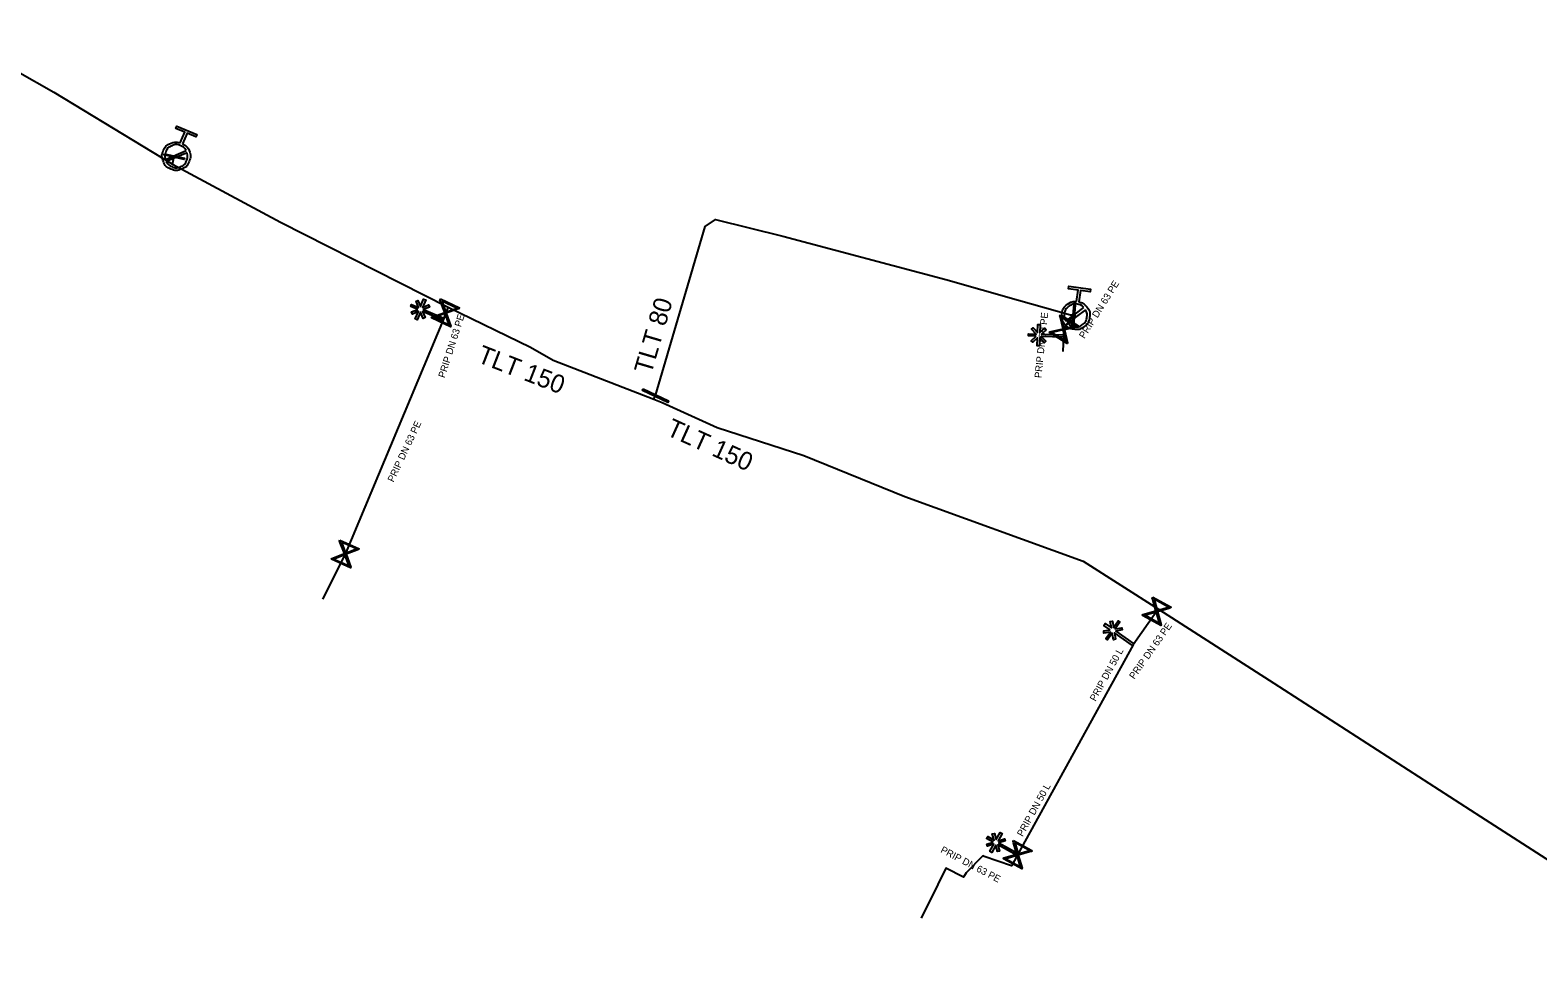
# Model space of a CAD drawing. Extents: x -643544 to -637295, y -1119190 to -1111715.
# Drawn here: x -642788.2 to -642680.3, y -1114459.1 to -1114393 of the extents above; entities that cross this region are included whole.
import ezdxf

# ---------------------------------------------------------------- set-up
doc = ezdxf.new("R2010")
doc.units = 0
for name, color, linetype in [('Default', 7, 'Continuous'), ('VP Hydrant', 7, 'Continuous'), ('VP Popis přípojky', 7, 'Continuous'), ('VP Přípojka', 7, 'Continuous'), ('VP Změna materiálu', 7, 'Continuous'), ('VP Řad', 7, 'Continuous'), ('VP Řad - popis', 7, 'Continuous'), ('VP Šoupě', 7, 'Continuous')]:
    doc.layers.add(name, color=color, linetype=linetype)

msp = doc.modelspace()

# ---------------------------------------------------------------- linework, layer by layer
at = {"layer": 'Default'}
for points in [[(-642777.26, -1114401.17), (-642776.93, -1114401.34), (-642776.79, -1114401.68), (-642776.64, -1114402.06), (-642776.8, -1114402.44), (-642776.95, -1114402.83), (-642777.34, -1114402.98), (-642777.72, -1114403.14), (-642778.1, -1114402.98), (-642778.48, -1114402.83), (-642778.64, -1114402.44), (-642778.8, -1114402.06), (-642778.65, -1114401.68), (-642778.49, -1114401.3), (-642778.11, -1114401.14), (-642777.77, -1114400.99), (-642777.43, -1114401.1)], [(-642777.01, -1114401.66), (-642777.14, -1114401.42), (-642777.41, -1114401.31), (-642777.72, -1114401.18), (-642778.03, -1114401.31), (-642778.34, -1114401.44), (-642778.47, -1114401.75), (-642778.58, -1114402.02), (-642778.5, -1114402.29)], [(-642778.43, -1114402.45), (-642778.3, -1114402.7), (-642778.03, -1114402.81), (-642777.72, -1114402.94), (-642777.41, -1114402.81), (-642777.1, -1114402.68), (-642776.97, -1114402.37), (-642776.86, -1114402.1), (-642776.94, -1114401.83)], [(-642713.12, -1114412.48), (-642712.77, -1114412.56), (-642712.55, -1114412.85), (-642712.3, -1114413.18), (-642712.36, -1114413.59), (-642712.42, -1114414), (-642712.75, -1114414.25), (-642713.08, -1114414.5), (-642713.49, -1114414.44), (-642713.9, -1114414.38), (-642714.15, -1114414.05), (-642714.4, -1114413.72), (-642714.34, -1114413.31), (-642714.28, -1114412.9), (-642713.95, -1114412.65), (-642713.66, -1114412.43), (-642713.3, -1114412.45)], [(-642712.76, -1114412.89), (-642712.95, -1114412.69), (-642713.24, -1114412.64), (-642713.57, -1114412.6), (-642713.84, -1114412.8), (-642714.11, -1114413), (-642714.16, -1114413.33), (-642714.2, -1114413.62), (-642714.05, -1114413.86)], [(-642713.94, -1114414.01), (-642713.75, -1114414.21), (-642713.47, -1114414.25), (-642713.13, -1114414.3), (-642712.86, -1114414.1), (-642712.6, -1114413.9), (-642712.55, -1114413.56), (-642712.51, -1114413.28), (-642712.65, -1114413.04)]]:
    msp.add_open_spline(points, degree=3, dxfattribs=at)
at = {"layer": 'VP Hydrant'}
for points in [[(-642777.43, -1114401.1), (-642777.11, -1114400.35), (-642777.75, -1114400.08), (-642777.68, -1114399.91), (-642776.24, -1114400.51), (-642776.31, -1114400.68), (-642776.94, -1114400.42), (-642777.26, -1114401.17)], [(-642778.5, -1114402.29), (-642777.01, -1114401.66)], [(-642776.94, -1114401.83), (-642778.43, -1114402.45)], [(-642713.3, -1114412.45), (-642713.18, -1114411.64), (-642713.87, -1114411.54), (-642713.84, -1114411.36), (-642712.29, -1114411.58), (-642712.32, -1114411.76), (-642713, -1114411.67), (-642713.12, -1114412.48)], [(-642714.05, -1114413.86), (-642712.76, -1114412.89)], [(-642712.65, -1114413.04), (-642713.94, -1114414.01)]]:
    msp.add_lwpolyline(points, dxfattribs=at)
at = {"layer": 'VP Přípojka'}
for points in [[(-642777.99, -1114402.62), (-642777.87, -1114402.09), (-642777.72, -1114402.06)], [(-642758.6, -1114413.71), (-642765.63, -1114430.52), (-642767.25, -1114433.75)], [(-642758.25, -1114412.85), (-642758.46, -1114413.27), (-642758.6, -1114413.71)], [(-642713.61, -1114413.42), (-642713.65, -1114413.55), (-642714.21, -1114414.44), (-642714.23, -1114414.93)], [(-642714.23, -1114414.93), (-642714.27, -1114416.04)], [(-642707.44, -1114434.46), (-642707.55, -1114434.62), (-642709.24, -1114437.01)], [(-642709.24, -1114437.01), (-642717.51, -1114452.03)], [(-642717.51, -1114452.03), (-642717.73, -1114452.44), (-642717.94, -1114452.83), (-642719.91, -1114452.16), (-642720.01, -1114452.11), (-642721.18, -1114453.32), (-642721.38, -1114453.63), (-642722.64, -1114452.99), (-642723.22, -1114454.17), (-642724.41, -1114456.58)]]:
    msp.add_lwpolyline(points, dxfattribs=at)
at = {"layer": 'VP Změna materiálu'}
for points in [[(-642760.44, -1114413.02), (-642760.94, -1114412.81), (-642760.88, -1114412.67), (-642760.38, -1114412.88), (-642760.56, -1114412.44), (-642760.42, -1114412.39), (-642760.24, -1114412.82), (-642760.02, -1114412.28), (-642759.87, -1114412.34), (-642760.1, -1114412.88), (-642759.66, -1114412.7), (-642759.6, -1114412.85), (-642760.03, -1114413.02), (-642758.57, -1114413.64), (-642758.63, -1114413.78), (-642760.09, -1114413.17), (-642759.91, -1114413.6), (-642760.06, -1114413.66), (-642760.24, -1114413.22), (-642760.47, -1114413.76), (-642760.61, -1114413.7), (-642760.39, -1114413.17), (-642760.82, -1114413.35), (-642760.88, -1114413.2), (-642760.44, -1114413.02)], [(-642716.19, -1114414.93), (-642716.73, -1114414.91), (-642716.72, -1114414.76), (-642716.19, -1114414.78), (-642716.51, -1114414.43), (-642716.39, -1114414.33), (-642716.08, -1114414.67), (-642716.06, -1114414.09), (-642715.9, -1114414.1), (-642715.92, -1114414.68), (-642715.57, -1114414.36), (-642715.47, -1114414.47), (-642715.81, -1114414.79), (-642714.22, -1114414.84), (-642714.23, -1114415), (-642715.82, -1114414.95), (-642715.49, -1114415.29), (-642715.61, -1114415.4), (-642715.93, -1114415.05), (-642715.95, -1114415.63), (-642716.11, -1114415.63), (-642716.09, -1114415.05), (-642716.43, -1114415.37), (-642716.53, -1114415.26), (-642716.19, -1114414.93)], [(-642710.89, -1114435.94), (-642711.33, -1114435.63), (-642711.24, -1114435.5), (-642710.8, -1114435.81), (-642710.88, -1114435.35), (-642710.73, -1114435.32), (-642710.65, -1114435.78), (-642710.31, -1114435.31), (-642710.19, -1114435.4), (-642710.52, -1114435.88), (-642710.06, -1114435.8), (-642710.03, -1114435.95), (-642710.49, -1114436.03), (-642709.19, -1114436.94), (-642709.28, -1114437.07), (-642710.58, -1114436.16), (-642710.5, -1114436.62), (-642710.65, -1114436.65), (-642710.74, -1114436.18), (-642711.07, -1114436.66), (-642711.2, -1114436.57), (-642710.87, -1114436.1), (-642711.33, -1114436.18), (-642711.35, -1114436.02), (-642710.89, -1114435.94)], [(-642719.26, -1114451.14), (-642719.73, -1114450.88), (-642719.65, -1114450.74), (-642719.18, -1114451), (-642719.32, -1114450.55), (-642719.17, -1114450.51), (-642719.04, -1114450.95), (-642718.76, -1114450.45), (-642718.62, -1114450.52), (-642718.9, -1114451.04), (-642718.45, -1114450.9), (-642718.41, -1114451.05), (-642718.85, -1114451.18), (-642717.46, -1114451.95), (-642717.54, -1114452.08), (-642718.93, -1114451.32), (-642718.8, -1114451.77), (-642718.95, -1114451.81), (-642719.08, -1114451.36), (-642719.36, -1114451.87), (-642719.5, -1114451.79), (-642719.22, -1114451.29), (-642719.67, -1114451.42), (-642719.71, -1114451.27), (-642719.26, -1114451.14)]]:
    msp.add_lwpolyline(points, dxfattribs=at)
at = {"layer": 'VP Řad'}
for points in [[(-642794.3, -1114393.04), (-642786.48, -1114397.48), (-642777.99, -1114402.62), (-642770.26, -1114406.77), (-642758.25, -1114412.85), (-642752.38, -1114415.72), (-642750.74, -1114416.66), (-642743.55, -1114419.45), (-642742.94, -1114419.68), (-642739, -1114421.46), (-642732.82, -1114423.48), (-642725.58, -1114426.4), (-642712.82, -1114431.02), (-642707.44, -1114434.46), (-642699.18, -1114439.75), (-642684.39, -1114449.31), (-642669.1, -1114459.12)], [(-642743.55, -1114419.45), (-642743.43, -1114419.19), (-642739.87, -1114407.08), (-642739.12, -1114406.59), (-642734.32, -1114407.77), (-642722.65, -1114410.88), (-642717.44, -1114412.35), (-642713.73, -1114413.41), (-642713.61, -1114413.42), (-642713.49, -1114413.43), (-642713.35, -1114413.45)]]:
    msp.add_lwpolyline(points, dxfattribs=at)
at = {"layer": 'VP Šoupě'}
for points in [[(-642778.59, -1114401.88), (-642777.13, -1114402.21), (-642777.15, -1114402.3), (-642778.61, -1114401.97), (-642778.59, -1114401.88)], [(-642758.82, -1114412.27), (-642757.46, -1114412.91), (-642757.49, -1114412.97), (-642757.61, -1114413.01), (-642758.4, -1114413.29), (-642758.07, -1114414.21), (-642758.1, -1114414.27), (-642759.46, -1114413.63), (-642759.43, -1114413.57), (-642758.51, -1114413.24), (-642758.8, -1114412.45), (-642758.85, -1114412.33), (-642758.82, -1114412.27)], [(-642758.72, -1114412.42), (-642758.43, -1114413.21), (-642757.64, -1114412.93), (-642758.72, -1114412.42)], [(-642713.38, -1114412.69), (-642713.51, -1114414.18), (-642713.6, -1114414.17), (-642713.47, -1114412.68), (-642713.38, -1114412.69)], [(-642758.2, -1114414.12), (-642758.48, -1114413.32), (-642759.28, -1114413.61), (-642758.2, -1114414.12)], [(-642714.45, -1114413.41), (-642713.18, -1114414.2), (-642713.21, -1114414.26), (-642713.34, -1114414.28), (-642714.16, -1114414.47), (-642713.94, -1114415.42), (-642713.97, -1114415.47), (-642715.24, -1114414.67), (-642715.21, -1114414.62), (-642714.26, -1114414.41), (-642714.45, -1114413.59), (-642714.48, -1114413.46), (-642714.45, -1114413.41)], [(-642714.36, -1114413.57), (-642714.18, -1114414.39), (-642713.36, -1114414.2), (-642714.36, -1114413.57)], [(-642714.05, -1114415.31), (-642714.24, -1114414.49), (-642715.06, -1114414.68), (-642714.05, -1114415.31)], [(-642744.31, -1114418.71), (-642742.5, -1114419.55), (-642742.55, -1114419.67), (-642744.36, -1114418.83), (-642744.31, -1114418.71)], [(-642766.01, -1114429.53), (-642764.64, -1114430.14), (-642764.67, -1114430.2), (-642764.79, -1114430.24), (-642765.57, -1114430.54), (-642765.22, -1114431.45), (-642765.25, -1114431.51), (-642766.62, -1114430.9), (-642766.59, -1114430.84), (-642765.68, -1114430.49), (-642765.99, -1114429.71), (-642766.03, -1114429.59), (-642766.01, -1114429.53)], [(-642765.9, -1114429.68), (-642765.6, -1114430.46), (-642764.82, -1114430.16), (-642765.9, -1114429.68)], [(-642765.35, -1114431.36), (-642765.65, -1114430.58), (-642766.44, -1114430.88), (-642765.35, -1114431.36)], [(-642707.84, -1114433.6), (-642706.53, -1114434.33), (-642706.56, -1114434.38), (-642706.69, -1114434.42), (-642707.5, -1114434.65), (-642707.23, -1114435.58), (-642707.26, -1114435.64), (-642708.57, -1114434.91), (-642708.54, -1114434.85), (-642707.61, -1114434.59), (-642707.84, -1114433.78), (-642707.88, -1114433.66), (-642707.84, -1114433.6)], [(-642707.75, -1114433.76), (-642707.52, -1114434.56), (-642706.72, -1114434.33), (-642707.75, -1114433.76)], [(-642707.35, -1114435.48), (-642707.58, -1114434.67), (-642708.39, -1114434.9), (-642707.35, -1114435.48)], [(-642717.8, -1114451.01), (-642716.49, -1114451.74), (-642716.52, -1114451.8), (-642716.65, -1114451.83), (-642717.46, -1114452.06), (-642717.19, -1114452.99), (-642717.22, -1114453.05), (-642718.53, -1114452.32), (-642718.5, -1114452.26), (-642717.56, -1114452), (-642717.8, -1114451.19), (-642717.83, -1114451.07), (-642717.8, -1114451.01)], [(-642717.71, -1114451.17), (-642717.48, -1114451.97), (-642716.67, -1114451.74), (-642717.71, -1114451.17)], [(-642717.31, -1114452.89), (-642717.54, -1114452.08), (-642718.35, -1114452.32), (-642717.31, -1114452.89)]]:
    msp.add_lwpolyline(points, dxfattribs=at)

# ---------------------------------------------------------------- texts
at = {"layer": 'VP Popis přípojky'}
for s, rotation, p in [('PRIP DN 63 PE', 57.8214, (-642712.73, -1114415.15)), ('PRIP DN 63 PE', 72.3498, (-642758.51, -1114417.96)), ('PRIP DN 50 PE', 84.0531, (-642715.81, -1114417.95)), ('PRIP DN 63 PE', 64.8032, (-642762.17, -1114425.42)), ('PRIP DN 63 PE', 54.7946, (-642709.16, -1114439.52)), ('PRIP DN 50 L', 61.1628, (-642711.94, -1114441.1)), ('PRIP DN 50 L', 61.1628, (-642717.15, -1114450.78)), ('PRIP DN 63 PE', 332.115, (-642723.07, -1114451.84))]:
    msp.add_text(s, height=0.5, rotation=rotation, dxfattribs=at).set_placement(p)
at = {"layer": 'VP Řad - popis'}
for s, rotation, p in [('TLT 80', 73.6181, (-642743.73, -1114417.71)), ('TLT 150', 338.7918, (-642756.26, -1114416.76)), ('TLT 150', 335.6877, (-642742.73, -1114421.97))]:
    msp.add_text(s, height=1.3, rotation=rotation, dxfattribs=at).set_placement(p)

doc.saveas('drawing.dxf')
